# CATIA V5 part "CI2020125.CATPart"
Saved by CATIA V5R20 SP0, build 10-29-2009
Part number: CI2020125
Bounding box of the stored display mesh (mm): x -19 to 19, y -14.509 to 155, z -26.066 to 21.271
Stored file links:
  C:\Users\Raffaele\Desktop\3D X SITO CF\BOLEX\19-INCLINED ASSEMBLY REF_CI\CI2020125.CATPart

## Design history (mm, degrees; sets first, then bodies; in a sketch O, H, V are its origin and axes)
Set1
  DatumSurface1 to DatumSurface16 "MANIFOLD_SOLID_BREP #387"
  DatumSurface17 to DatumSurface39 "MANIFOLD_SOLID_BREP #1116"
Body1 (main body)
